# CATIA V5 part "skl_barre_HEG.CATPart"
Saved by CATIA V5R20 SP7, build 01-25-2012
Part number: skl_barre_HEG
Publications: "Point.H", "Point.G", "Droite.1", "Droite.2", "Droite.3", "Droite.4"
Bounding box of the stored display mesh (mm): x -150 to 150, y 0 to 0, z -20 to 0
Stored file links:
  D:\IFMA\COURS\2A\projet balance IAO\catia\skl_barre_HEG.CATPart
  D:\IFMA\COURS\2A\projet balance IAO\catia\Skl_projet_balance.CATProduct
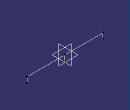
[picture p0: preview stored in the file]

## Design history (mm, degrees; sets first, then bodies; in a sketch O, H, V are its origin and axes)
Set1
  Point1 "Point.E": linked copy from another document
  Point2 "Point.H": linked copy from another document
  Point3 "Point.G": linked copy from another document
Body1 (main body)
  Point4 "Point.H": stored without definition
  Point5 "Point.G": stored without definition
  Line1: type PtPt, FirstPoint Point2, SecondPoint Point3
  Line2: type PtDir, RefPoint Point1, Direction xy-plane, Start 0, End 20
  Line3: type PtDir, RefPoint Point2, Direction xy-plane, Start 0, End 20
  Line4: type PtDir, RefPoint Point3, Direction xy-plane, Start 0, End 20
